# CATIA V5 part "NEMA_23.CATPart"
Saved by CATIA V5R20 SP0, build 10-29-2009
Part number: NEMA_23
Bounding box of the stored display mesh (mm): x -31.534 to 24.866, y -36.51 to 21.89, z 14.8 to 95.3
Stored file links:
  C:\Users\Andi\Desktop\Offene Projekte\Plasmacutter\Z-Achse\NEMA_23.CATPart
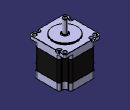
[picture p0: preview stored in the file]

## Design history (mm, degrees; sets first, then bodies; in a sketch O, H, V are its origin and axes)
Body1 (main body)
Body2 "NAUO10\\Répétition circulaire1"
  Solid1: solid without history
Body3 "NAUO8\\Enlèv. mat.-Extru.3"
  Solid2 "Volumen.1": solid without history
Body4 "NAUO5\\Enlèv. mat.-Extru.1"
  Solid3 "Volumen.1": solid without history
Body5 "NAUO3\\Congé1"
  Solid4 "Volumen.1": solid without history
Body6 "NAUO7\\Congé2"
  Solid5 "Volumen.1": solid without history
Body7 "NAUO2\\Répétition circulaire1"
  Solid6 "Volumen.1": solid without history
Body8 "NAUO6\\Enlèv. mat.-Extru.1"
  Solid7 "Volumen.1": solid without history
Body9 "NAUO4\\Enlèv. mat.-Extru.4"
  Solid8 "Volumen.1": solid without history
Body10 "NAUO9\\Répétition circulaire1"
  Solid9 "Volumen.1": solid without history
Body11 "NAUO1\\Répétition circulaire1"
  Solid10 "Volumen.1": solid without history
